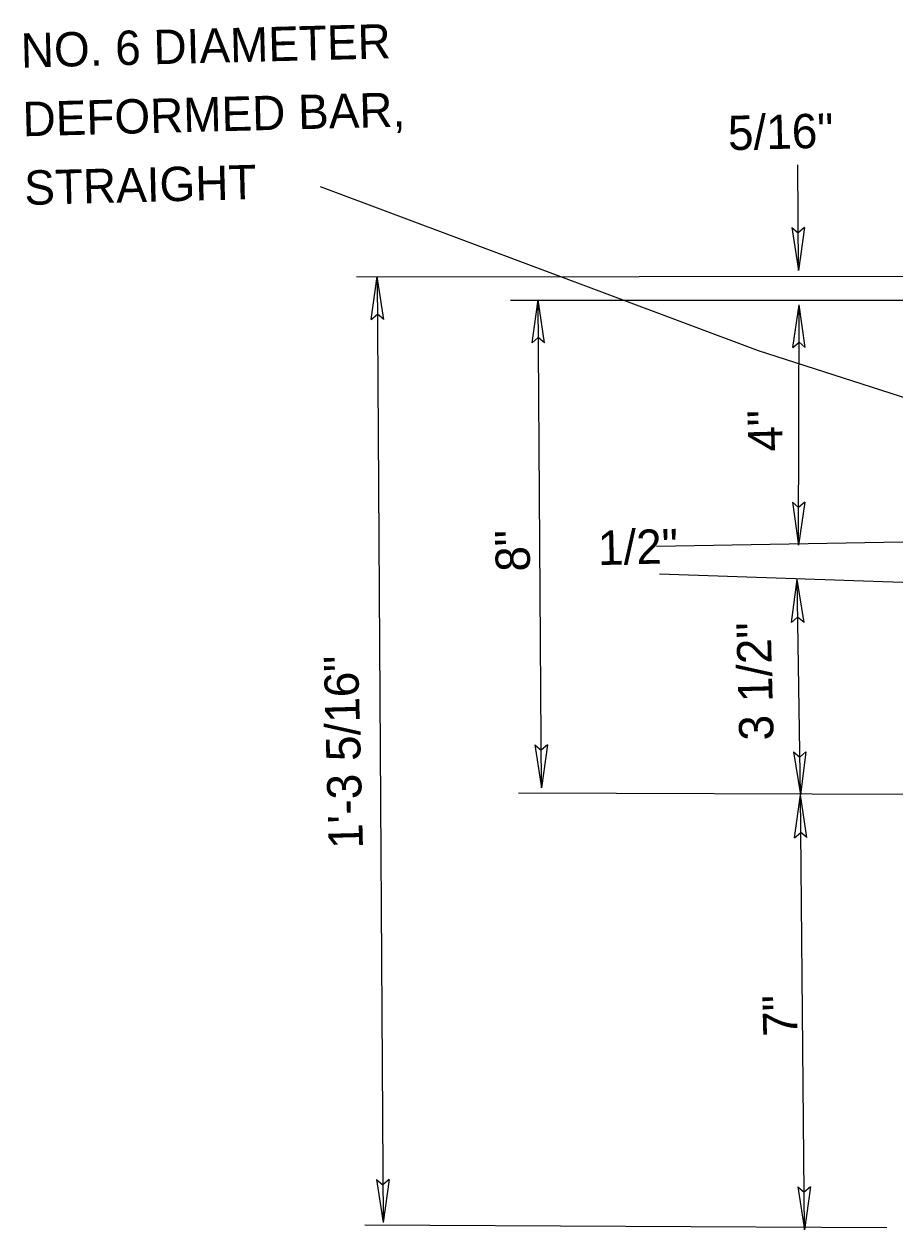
# Model space of a CAD drawing. Extents: x 1.75 to 8.12, y 0.37 to 10.28.
# Drawn here: x 2.139 to 3.66, y 3.215 to 5.322 of the extents above; entities that cross this region are included whole.
import ezdxf

# ---------------------------------------------------------------- set-up
doc = ezdxf.new("R2010")
doc.units = 0
doc.layers.add('DETL-DIMS', color=7, linetype='Continuous')
doc.layers.add('DETL-NOTE', color=7, linetype='Continuous')

msp = doc.modelspace()

# ---------------------------------------------------------------- linework, layer by layer
at = {"layer": 'DETL-DIMS'}
for p, q in [((3.4917, 4.8919), (3.491, 5.076)), ((3.4805, 4.9669), (3.4917, 4.8919)), ((3.4805, 4.9669), (3.4914, 4.9576)), ((3.5023, 4.967), (3.4914, 4.9576)), ((3.5023, 4.967), (3.4917, 4.8919)), ((4.812, 4.8817), (2.7199, 4.8802)), ((2.7454, 4.806), (2.7559, 4.8811)), ((2.7559, 4.8811), (2.7662, 3.2284)), ((2.7673, 4.8062), (2.7559, 4.8811)), ((3.7691, 4.839), (2.989, 4.839)), ((3.0265, 4.7652), (3.037, 4.8403)), ((3.0428, 3.9879), (3.037, 4.8403)), ((3.0484, 4.7653), (3.037, 4.8403)), ((3.4821, 4.757), (3.4932, 4.8319)), ((3.492, 4.4117), (3.4932, 4.8319)), ((3.5039, 4.7569), (3.4932, 4.8319)), ((2.7454, 4.806), (2.7563, 4.8155)), ((2.7673, 4.8062), (2.7563, 4.8155)), ((3.0265, 4.7652), (3.0374, 4.7746)), ((3.0484, 4.7653), (3.0374, 4.7746)), ((3.4821, 4.757), (3.493, 4.7663)), ((3.5039, 4.7569), (3.493, 4.7663)), ((3.4813, 4.4867), (3.492, 4.4117)), ((3.4813, 4.4867), (3.4922, 4.4773)), ((3.5032, 4.4867), (3.492, 4.4117)), ((3.5032, 4.4867), (3.4922, 4.4773)), ((3.7158, 4.4174), (3.244, 4.4093)), ((3.2493, 4.3614), (3.9859, 4.3363)), ((3.4797, 4.2764), (3.4895, 4.3516)), ((3.4952, 3.9755), (3.4895, 4.3516)), ((3.5016, 4.2767), (3.4895, 4.3516)), ((3.4797, 4.2764), (3.4905, 4.2859)), ((3.5016, 4.2767), (3.4905, 4.2859)), ((3.0314, 4.0629), (3.0428, 3.9879)), ((3.0314, 4.0629), (3.0424, 4.0536)), ((3.0532, 4.063), (3.0424, 4.0536)), ((3.0532, 4.063), (3.0428, 3.9879)), ((3.4831, 4.0503), (3.4952, 3.9755)), ((3.4831, 4.0503), (3.4942, 4.0411)), ((3.505, 4.0507), (3.4942, 4.0411)), ((3.505, 4.0507), (3.4952, 3.9755)), ((3.003, 3.9789), (3.6871, 3.9764)), ((3.485, 3.9004), (3.4952, 3.9755)), ((3.5026, 3.2153), (3.4952, 3.9755)), ((3.5068, 3.9006), (3.4952, 3.9755)), ((3.485, 3.9004), (3.4958, 3.9099)), ((3.5068, 3.9006), (3.4958, 3.9099)), ((2.7548, 3.3033), (2.7662, 3.2284)), ((2.7548, 3.3033), (2.7658, 3.294)), ((2.7767, 3.3035), (2.7658, 3.294)), ((2.7767, 3.3035), (2.7662, 3.2284)), ((3.491, 3.2902), (3.5027, 3.2153)), ((3.491, 3.2902), (3.502, 3.2809)), ((3.5128, 3.2904), (3.502, 3.2809)), ((3.5128, 3.2904), (3.5027, 3.2153)), ((3.6465, 3.2189), (2.7344, 3.2236))]:
    msp.add_line(p, q, dxfattribs=at)
msp.add_lwpolyline([(2.6566, 5.0382), (3.4214, 4.7518), (3.8508, 4.614)], dxfattribs=at)

# ---------------------------------------------------------------- texts
at = {"layer": 'DETL-NOTE'}
for s, rotation, p in [('NO. 6 DIAMETER ', 1.4676, (2.1341, 5.246)), ('DEFORMED BAR, ', 1.4676, (2.1372, 5.1261)), ('5/16"', 1.4676, (3.3694, 5.1018)), ('STRAIGHT', 1.4676, (2.1402, 5.0061)), ('4"', 91.4676, (3.4645, 4.5759)), ('8"', 91.4676, (3.0233, 4.3661)), ('1/2"', 1.4676, (3.1423, 4.3768)), ('3 1/2"', 91.4676, (3.4486, 4.071)), ('1\'-3 5/16"', 91.4676, (2.7312, 3.8816)), ('7"', 91.4676, (3.4905, 3.5537))]:
    msp.add_text(s, height=0.06, rotation=rotation, dxfattribs=at).set_placement(p)

doc.saveas('drawing.dxf')
